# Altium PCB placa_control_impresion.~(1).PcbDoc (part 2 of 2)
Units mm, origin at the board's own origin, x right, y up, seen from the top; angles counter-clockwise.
Board outline 71.3 x 86.83 mm, 2 copper layers (Top Layer, Bottom Layer); 144 components, 32 nets, 580 pads, 404 vias.
Unrouted connection lines stored in the file: 1.
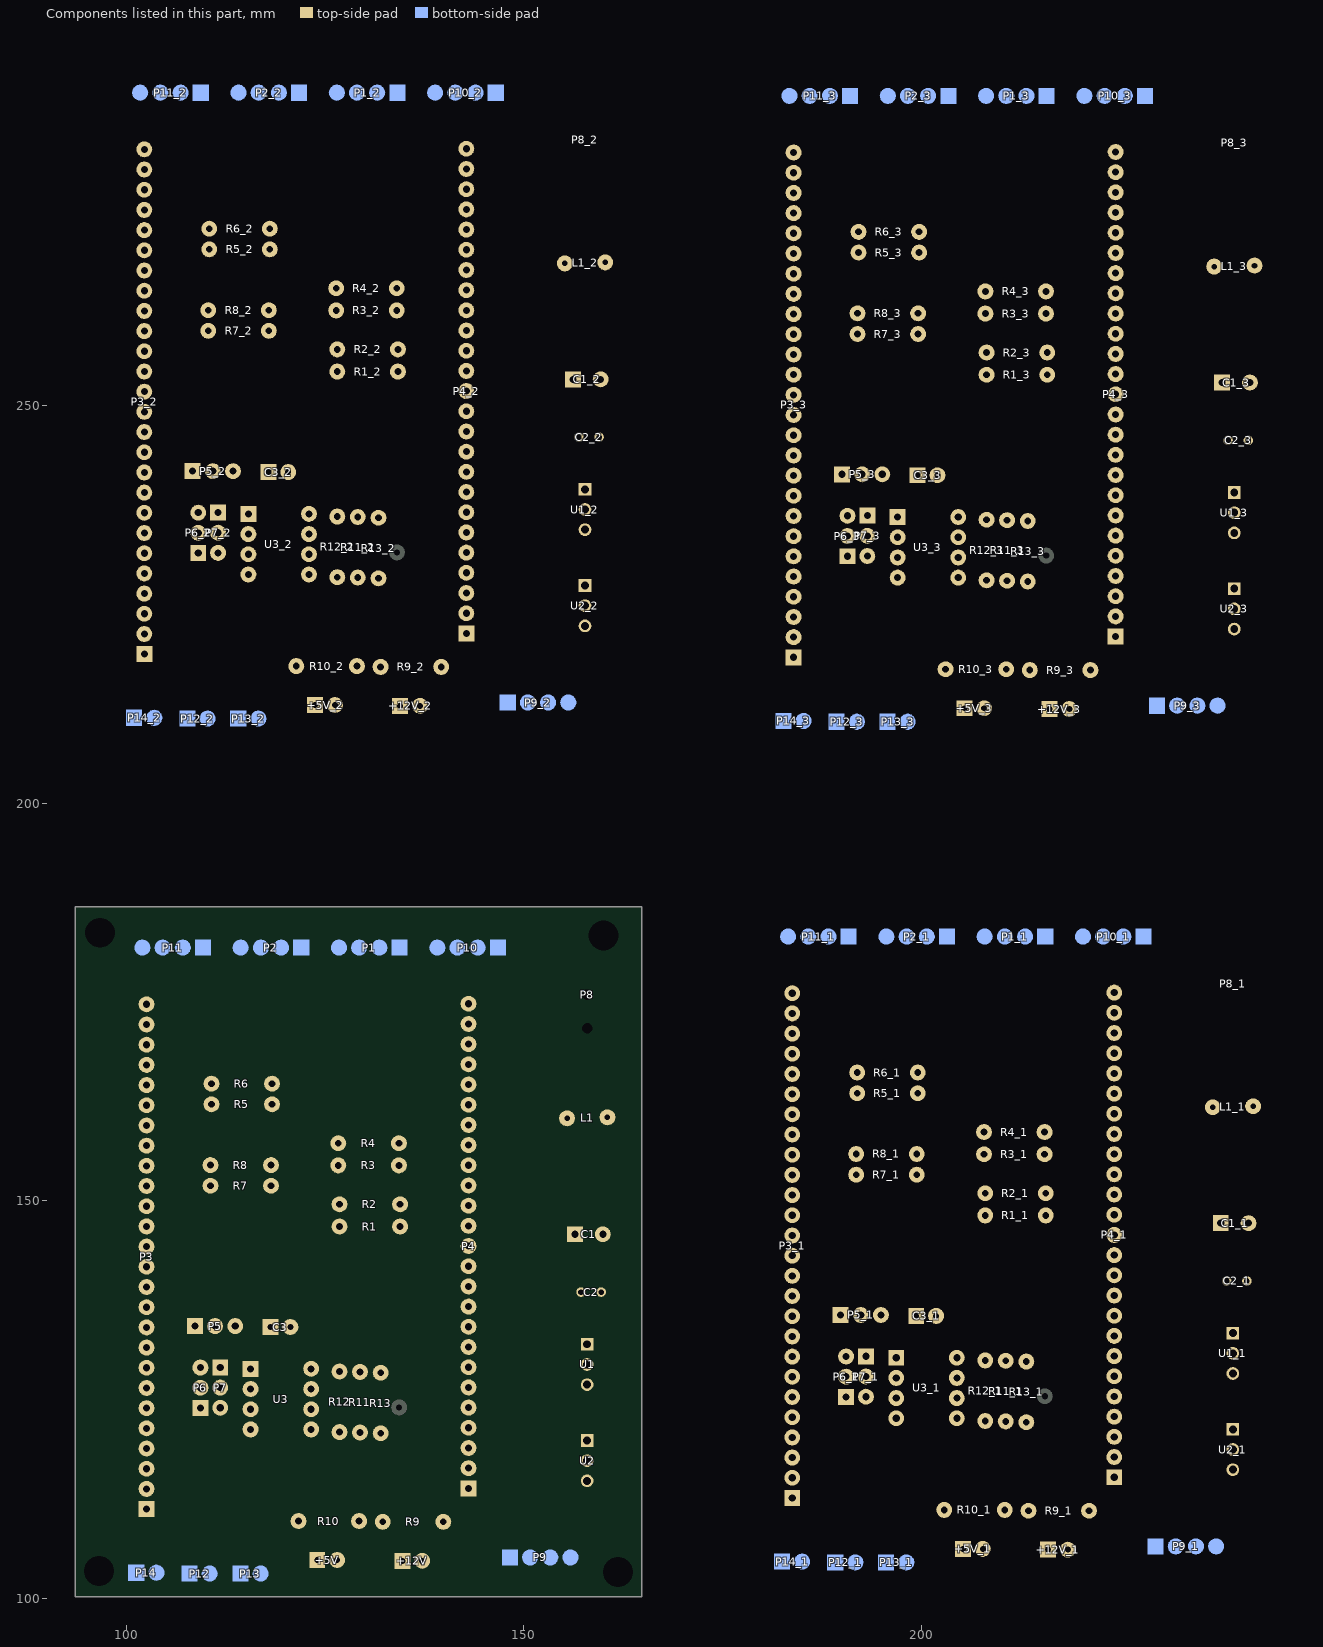
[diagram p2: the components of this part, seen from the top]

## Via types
v1: diameter 2, hole 0.711, Top Layer to Bottom Layer, 404 vias

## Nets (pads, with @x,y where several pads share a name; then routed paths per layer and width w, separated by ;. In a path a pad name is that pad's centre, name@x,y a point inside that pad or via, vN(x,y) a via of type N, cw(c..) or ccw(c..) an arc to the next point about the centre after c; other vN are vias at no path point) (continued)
pads on no net: +5V_1.1 +5V_1.2 +5V_2.1 +5V_2.2 +5V_3.1 +5V_3.2 +12V_1.1 +12V_1.2 +12V_2.1 +12V_2.2 +12V_3.1 +12V_3.2 C1_1.1 C1_1.2 C1_2.1 C1_2.2 C1_3.1 C1_3.2 C2_1.1 C2_1.2 C2_2.1 C2_2.2 C2_3.1 C2_3.2 C3_1.1 C3_1.2 C3_2.1 C3_2.2 C3_3.1 C3_3.2 L1_1.1 L1_1.2 L1_2.1 L1_2.2 L1_3.1 L1_3.2 P1_1.1 P1_1.2 P1_1.3 P1_1.4 P1_2.1 P1_2.2 P1_2.3 P1_2.4 P1_3.1 P1_3.2 P1_3.3 P1_3.4 P2_1.1 P2_1.2 P2_1.3 P2_1.4 P2_2.1 P2_2.2 P2_2.3 P2_2.4 P2_3.1 P2_3.2 P2_3.3 P2_3.4 P3.3 P3.4 P3.5 P3.10 P3.11 P3.12 P3.13 P3.18 P3.19 P3.22 P3.23 P3.24 P3.25 P3.26 P3_1.1 P3_1.2 P3_1.3 P3_1.4 P3_1.5 P3_1.6 P3_1.7 P3_1.8 P3_1.9 P3_1.10 P3_1.11 P3_1.12 P3_1.13 P3_1.14 P3_1.15 P3_1.16 P3_1.17 P3_1.18 P3_1.19 P3_1.20 P3_1.21 P3_1.22 P3_1.23 P3_1.24 P3_1.25 P3_1.26 P3_2.1 P3_2.2 P3_2.3 P3_2.4 P3_2.5 P3_2.6 P3_2.7 P3_2.8 P3_2.9 P3_2.10 P3_2.11 P3_2.12 P3_2.13 P3_2.14 P3_2.15 P3_2.16 P3_2.17 P3_2.18 P3_2.19 P3_2.20 P3_2.21 P3_2.22 P3_2.23 P3_2.24 P3_2.25 P3_2.26 P3_3.1 P3_3.2 P3_3.3 P3_3.4 P3_3.5 P3_3.6 P3_3.7 P3_3.8 P3_3.9 P3_3.10 P3_3.11 P3_3.12 P3_3.13 P3_3.14 P3_3.15 P3_3.16 P3_3.17 P3_3.18 P3_3.19 P3_3.20 P3_3.21 P3_3.22 P3_3.23 P3_3.24 P3_3.25 P3_3.26 P4.3 P4.4 P4.6 P4.7 P4.8 P4.9 P4.10 P4.11 P4.12 P4.13 P4.18 P4.19 P4.20 P4.22 P4.23 P4.24 P4.25 P4_1.1 P4_1.2 P4_1.3 P4_1.4 P4_1.5 P4_1.6 P4_1.7 P4_1.8 P4_1.9 P4_1.10 P4_1.11 P4_1.12 P4_1.13 P4_1.14 P4_1.15 P4_1.16 P4_1.17 P4_1.18 P4_1.19 P4_1.20 P4_1.21 P4_1.22 P4_1.23 P4_1.24 P4_1.25 P4_2.1 P4_2.2 P4_2.3 P4_2.4 P4_2.5 P4_2.6 P4_2.7 P4_2.8 P4_2.9 P4_2.10 P4_2.11 P4_2.12 P4_2.13 P4_2.14 P4_2.15 P4_2.16 P4_2.17 P4_2.18 P4_2.19 P4_2.20 P4_2.21 P4_2.22 P4_2.23 P4_2.24 P4_2.25 P4_3.1 P4_3.2 P4_3.3 P4_3.4 P4_3.5 P4_3.6 P4_3.7 P4_3.8 P4_3.9 P4_3.10 P4_3.11 P4_3.12 P4_3.13 P4_3.14 P4_3.15 P4_3.16 P4_3.17 P4_3.18 P4_3.19 P4_3.20 P4_3.21 P4_3.22 P4_3.23 P4_3.24 P4_3.25 P5_1.1 P5_1.2 P5_1.3 P5_2.1 P5_2.2 P5_2.3 P5_3.1 P5_3.2 P5_3.3 P6_1.1 P6_1.2 P6_1.3 P6_2.1 P6_2.2 P6_2.3 P6_3.1 P6_3.2 P6_3.3 P7_1.1 P7_1.2 P7_1.3 P7_2.1 P7_2.2 P7_2.3 P7_3.1 P7_3.2 P7_3.3 P8_1.2 P8_2.2 P8_3.2 P9_1.1 P9_1.2 P9_1.3 P9_1.4 P9_2.1 P9_2.2 P9_2.3 P9_2.4 P9_3.1 P9_3.2 P9_3.3 P9_3.4 P10_1.1 P10_1.2 P10_1.3 P10_1.4 P10_2.1 P10_2.2 P10_2.3 P10_2.4 P10_3.1 P10_3.2 P10_3.3 P10_3.4 P11_1.1 P11_1.2 P11_1.3 P11_1.4 P11_2.1 P11_2.2 P11_2.3 P11_2.4 P11_3.1 P11_3.2 P11_3.3 P11_3.4 P12_1.1 P12_1.2 P12_2.1 P12_2.2 P12_3.1 P12_3.2 P13_1.1 P13_1.2 P13_2.1 P13_2.2 P13_3.1 P13_3.2 P14_1.1 P14_1.2 P14_2.1 P14_2.2 P14_3.1 P14_3.2 R1_1.1 R1_1.2 R1_2.1 R1_2.2 R1_3.1 R1_3.2 R2_1.1 R2_1.2 R2_2.1 R2_2.2 R2_3.1 R2_3.2 R3_1.1 R3_1.2 R3_2.1 R3_2.2 R3_3.1 R3_3.2 R4_1.1 R4_1.2 R4_2.1 R4_2.2 R4_3.1 R4_3.2 R5_1.1 R5_1.2 R5_2.1 R5_2.2 R5_3.1 R5_3.2 R6_1.1 R6_1.2 R6_2.1 R6_2.2 R6_3.1 R6_3.2 R7_1.1 R7_1.2 R7_2.1 R7_2.2 R7_3.1 R7_3.2 R8_1.1 R8_1.2 R8_2.1 R8_2.2 R8_3.1 R8_3.2 R9_1.1 R9_1.2 R9_2.1 R9_2.2 R9_3.1 R9_3.2 R10_1.1 R10_1.2 R10_2.1 R10_2.2 R10_3.1 R10_3.2 R11_1.1 R11_1.2 R11_2.1 R11_2.2 R11_3.1 R11_3.2 R12_1.1 R12_1.2 R12_2.1 R12_2.2 R12_3.1 R12_3.2 R13_1.1 R13_1.2 R13_2.1 R13_2.2 R13_3.1 R13_3.2 U1_1.1 U1_1.2 U1_1.3 U1_2.1 U1_2.2 U1_2.3 U1_3.1 U1_3.2 U1_3.3 U2_1.1 U2_1.2 U2_1.3 U2_2.1 U2_2.2 U2_2.3 U2_3.1 U2_3.2 U2_3.3 U3_1.1 U3_1.2 U3_1.3 U3_1.4 U3_1.5 U3_1.6 U3_1.7 U3_1.8 U3_2.1 U3_2.2 U3_2.3 U3_2.4 U3_2.5 U3_2.6 U3_2.7 U3_2.8 U3_3.1 U3_3.2 U3_3.3 U3_3.4 U3_3.5 U3_3.6 U3_3.7 U3_3.8
copper on no net: | length 3999.1
  Bottom Layer w0.8: v1@98.525,269.65 110.43,269.65 110.44,269.64 110.44,272.3 ; v1(98.625,259.5) 97.15,259.5 96.175,258.525 96.175,219.75 97.135,218.79 v1(98.695,218.79) ; v1@98.625,272.19 v1@105.94,272.19 ; v1@98.665,221.39 v1@105.85,221.39 ; v1@98.665,223.93 v1@105.85,223.93 ; v1@98.665,226.47 v1@105.85,226.47 ; v1@98.665,229.01 v1@105.85,229.01 ; v1@98.665,231.55 109,231.55 109.05,231.5 ; v1@98.665,234.09 109,234.09 109.05,234.04 ; v1@98.665,236.63 109,236.63 109.05,236.58 ; v1(98.665,239.17) 107.395,239.17 108.225,240 114.225,240 115.4,241.175 115.4,254.95 113.825,256.525 113.825,279.675 109.37,284.13 109.37,289.405 ; v1@98.665,241.71 v1@105.825,241.71 ; v1@98.665,244.25 v1@105.85,244.25 ; v1@98.665,246.79 v1@105.85,246.79 ; v1@98.665,249.33 v1@105.85,249.33 ; v1(98.665,251.87) 106.73,251.87 108.35,250.25 108.35,241.8 ; v1(98.665,254.41) 107.115,254.41 110.89,250.635 110.89,241.8 ; v1(98.665,256.95) v1(105.85,256.95) ; v1@98.665,259.49 v1@105.85,259.49 ; v1@98.665,262.03 v1@105.85,262.03 ; v1@98.665,264.57 v1@105.85,264.57 ; v1@98.665,267.11 v1@105.85,267.11 ; v1@98.665,274.73 v1@105.85,274.73 ; v1@98.665,277.27 v1@105.85,277.27 ; v1@98.665,279.81 v1@105.85,279.81 ; v1@98.665,282.35 v1@105.85,282.35 ; v1@98.735,218.78 v1@105.92,218.78 ; v1@98.9,164.64 v1@106.215,164.64 ; v1@98.94,116.38 v1@106.125,116.38 ; v1@98.94,118.92 v1@106.125,118.92 ; v1@98.94,121.46 v1@106.125,121.46 ; v1@98.94,134.16 v1@106.1,134.16 ; v1@98.94,136.7 v1@106.125,136.7 ; v1@98.94,139.24 v1@106.125,139.24 ; v1@98.94,141.78 v1@106.125,141.78 ; v1@98.94,154.48 v1@106.125,154.48 ; v1@98.94,157.02 v1@106.125,157.02 ; v1@98.94,167.18 v1@106.125,167.18 ; v1@98.94,169.72 v1@106.125,169.72 ; v1@98.94,172.26 v1@106.125,172.26 ; v1@98.94,174.8 v1@106.125,174.8 ; 103.625,210.88 103.52,210.775 103.52,212.545 108.525,217.55 108.525,220.525 107.635,221.415 v1(105.825,221.415) ; v1(105.825,259.515) 110.21,259.515 110.375,259.35 ; v1(105.825,267.135) 110.56,267.135 112.625,269.2 112.625,279.175 106.83,284.97 106.83,289.405 ; v1@105.875,257.05 108.475,257.05 113.43,252.095 113.43,241.8 ; 110.315,259.45 110.315,262.05 ; 114.117,289.405 114.117,283.983 115.025,283.075 115.025,260.8 116.375,259.45 117.935,259.45 ; 115.359,228.805 116.53,228.805 116.912,229.187 ; 115.359,231.345 115.435,231.42 115.435,233.915 115.475,233.875 ; 116.62,210.675 116.62,217.377 122.089,222.845 124.395,222.845 126.2,224.65 130.9,224.65 134.125,227.875 134.125,231.55 ; 116.657,289.405 116.657,283.984 116.225,283.552 116.225,271.535 118.06,269.7 ; 121.39,217.275 121.675,217.275 123.75,215.2 123.75,212.375 ; 126.399,262.018 127.568,262.018 128.45,262.9 128.45,269.875 126.45,271.875 126.45,288.65 ; 126.549,254.327 129.65,257.428 129.65,270.375 129.15,270.875 129.15,289.375 ; 131.99,217.175 134.45,214.715 134.45,212.275 ; 133.95,264.925 133.95,262.087 134.019,262.018 138.942,262.018 138.96,262 v1(138.975,262.015) ; 134.019,264.81 134.019,270.194 136,272.175 v1(138.975,272.175) ; 134.169,254.327 138.907,254.327 v1(138.975,254.395) 136.005,254.395 135.95,254.45 ; 134.2,254.45 134.2,257.3 ; v1(138.975,256.935) 137.015,256.935 134.65,259.3 133.725,259.3 132.125,260.9 132.125,280.125 137.075,285.075 142.45,285.075 143.93,286.555 143.93,289.405 ; v1@139.28,221.39 v1@146.465,221.39 ; v1@139.28,226.47 v1@146.465,226.47 ; v1@139.28,229.01 v1@146.465,229.01 ; v1@139.28,231.55 v1@146.465,231.55 ; v1@139.28,234.09 v1@146.465,234.09 ; v1@139.28,236.63 v1@146.465,236.63 ; v1@139.28,239.17 v1@146.465,239.17 ; v1@139.28,241.71 v1@146.465,241.71 ; v1@139.28,244.25 v1@146.465,244.25 ; v1@139.28,246.79 v1@146.465,246.79 ; v1@139.28,249.33 v1@146.465,249.33 ; v1@139.28,251.87 v1@146.465,251.87 ; v1@139.28,254.41 v1@146.465,254.41 ; v1@139.28,256.95 v1@146.465,256.95 ; v1@139.28,259.49 147.04,259.49 148.4,260.85 148.4,284.45 146.47,286.38 146.47,289.405 ; v1@139.28,262.03 v1@146.465,262.03 ; v1@139.28,264.57 v1@146.465,264.57 ; v1@139.28,267.11 v1@146.465,267.11 ; v1@139.28,269.65 v1@146.465,269.65 ; v1@139.28,272.19 v1@146.465,272.19 ; v1@139.28,274.73 v1@146.465,274.73 ; v1@139.28,277.27 v1@146.465,277.27 ; v1@139.28,279.81 v1@146.465,279.81 ; v1@139.28,282.35 v1@146.465,282.35 ; v1@139.555,118.92 v1@146.74,118.92 ; v1@139.555,121.46 v1@146.74,121.46 ; v1@139.555,126.54 v1@146.74,126.54 ; v1@139.555,129.08 v1@146.74,129.08 ; v1@139.555,131.62 v1@146.74,131.62 ; v1@139.555,134.16 v1@146.74,134.16 ; v1@139.555,136.7 v1@146.74,136.7 ; v1@139.555,139.24 v1@146.74,139.24 ; v1@139.555,141.78 v1@146.74,141.78 ; v1@139.555,144.32 v1@146.74,144.32 ; v1@139.555,157.02 v1@146.74,157.02 ; v1@139.555,159.56 v1@146.74,159.56 ; v1@139.555,162.1 v1@146.74,162.1 ; v1@139.555,167.18 v1@146.74,167.18 ; v1@139.555,169.72 v1@146.74,169.72 ; v1@139.555,172.26 v1@146.74,172.26 ; v1@139.555,174.8 v1@146.74,174.8 ; 139.61,217.175 139.61,213.565 143.625,209.55 153.275,209.55 155.6,211.875 155.6,212.695 ; v1@180.025,163.5 191.93,163.5 191.94,163.49 191.94,166.15 ; v1(180.125,153.35) 178.65,153.35 177.675,152.375 177.675,113.6 178.635,112.64 v1(180.195,112.64) ; v1@180.125,166.04 v1@187.44,166.04 ; v1@180.165,115.24 v1@187.35,115.24 ; v1@180.165,117.78 v1@187.35,117.78 ; v1@180.165,120.32 v1@187.35,120.32 ; v1@180.165,122.86 v1@187.35,122.86 ; v1@180.165,125.4 190.5,125.4 190.55,125.35 ; v1@180.165,127.94 190.5,127.94 190.55,127.89 ; v1@180.165,130.48 190.5,130.48 190.55,130.43 ; v1(180.165,133.02) 188.895,133.02 189.725,133.85 195.725,133.85 196.9,135.025 196.9,148.8 195.325,150.375 195.325,173.525 190.87,177.98 190.87,183.255 ; v1@180.165,135.56 v1@187.325,135.56 ; v1@180.165,138.1 v1@187.35,138.1 ; v1@180.165,140.64 v1@187.35,140.64 ; v1@180.165,143.18 v1@187.35,143.18 ; v1(180.165,145.72) 188.23,145.72 189.85,144.1 189.85,135.65 ; v1(180.165,148.26) 188.615,148.26 192.39,144.485 192.39,135.65 ; v1(180.165,150.8) v1(187.35,150.8) ; v1@180.165,153.34 v1@187.35,153.34 ; v1@180.165,155.88 v1@187.35,155.88 ; v1@180.165,158.42 v1@187.35,158.42 ; v1@180.165,160.96 v1@187.35,160.96 ; v1@180.165,168.58 v1@187.35,168.58 ; v1@180.165,171.12 v1@187.35,171.12 ; v1@180.165,173.66 v1@187.35,173.66 ; v1@180.165,176.2 v1@187.35,176.2 ; v1@180.2,269.25 192.105,269.25 192.115,269.24 192.115,271.9 ; v1@180.235,112.63 v1@187.42,112.63 ; v1(180.3,259.1) 178.825,259.1 177.85,258.125 177.85,219.35 178.81,218.39 v1(180.37,218.39) ; v1@180.3,271.79 v1@187.615,271.79 ; v1@180.34,220.99 v1@187.525,220.99 ; v1@180.34,223.53 v1@187.525,223.53 ; v1@180.34,226.07 v1@187.525,226.07 ; v1@180.34,228.61 v1@187.525,228.61 ; v1@180.34,231.15 190.675,231.15 190.725,231.1 ; v1@180.34,233.69 190.675,233.69 190.725,233.64 ; v1@180.34,236.23 190.675,236.23 190.725,236.18 ; v1(180.34,238.77) 189.07,238.77 189.9,239.6 195.9,239.6 197.075,240.775 197.075,254.55 195.5,256.125 195.5,279.275 191.045,283.73 191.045,289.005 ; v1@180.34,241.31 v1@187.5,241.31 ; v1@180.34,243.85 v1@187.525,243.85 ; v1@180.34,246.39 v1@187.525,246.39 ; v1@180.34,248.93 v1@187.525,248.93 ; v1(180.34,251.47) 188.405,251.47 190.025,249.85 190.025,241.4 ; v1(180.34,254.01) 188.79,254.01 192.565,250.235 192.565,241.4 ; v1(180.34,256.55) v1(187.525,256.55) ; v1@180.34,259.09 v1@187.525,259.09 ; v1@180.34,261.63 v1@187.525,261.63 ; v1@180.34,264.17 v1@187.525,264.17 ; v1@180.34,266.71 v1@187.525,266.71 ; v1@180.34,274.33 v1@187.525,274.33 ; v1@180.34,276.87 v1@187.525,276.87 ; v1@180.34,279.41 v1@187.525,279.41 ; v1@180.34,281.95 v1@187.525,281.95 ; v1@180.41,218.38 v1@187.595,218.38 ; 185.125,104.73 185.02,104.625 185.02,106.395 190.025,111.4 190.025,114.375 189.135,115.265 v1(187.325,115.265) ; 185.3,210.48 185.195,210.375 185.195,212.145 190.2,217.15 190.2,220.125 189.31,221.015 v1(187.5,221.015) ; v1(187.325,153.365) 191.71,153.365 191.875,153.2 ; v1(187.325,160.985) 192.06,160.985 194.125,163.05 194.125,173.025 188.33,178.82 188.33,183.255 ; v1@187.375,150.9 189.975,150.9 194.93,145.945 194.93,135.65 ; v1(187.5,259.115) 191.885,259.115 192.05,258.95 ; v1(187.5,266.735) 192.235,266.735 194.3,268.8 194.3,278.775 188.505,284.57 188.505,289.005 ; v1@187.55,256.65 190.15,256.65 195.105,251.695 195.105,241.4 ; 191.815,153.3 191.815,155.9 ; 191.99,259.05 191.99,261.65 ; 195.617,183.255 195.617,177.833 196.525,176.925 196.525,154.65 197.875,153.3 199.435,153.3 ; 195.792,289.005 195.792,283.583 196.7,282.675 196.7,260.4 198.05,259.05 199.61,259.05 ; 196.859,122.655 198.03,122.655 198.412,123.037 ; 196.859,125.195 196.935,125.27 196.935,127.765 196.975,127.725 ; 197.034,228.405 198.205,228.405 198.587,228.787 ; 197.034,230.945 197.11,231.02 197.11,233.515 197.15,233.475 ; 198.12,104.525 198.12,111.227 203.589,116.695 205.895,116.695 207.7,118.5 212.4,118.5 215.625,121.725 215.625,125.4 ; 198.157,183.255 198.157,177.834 197.725,177.402 197.725,165.385 199.56,163.55 ; 198.295,210.275 198.295,216.977 203.764,222.445 206.07,222.445 207.875,224.25 212.575,224.25 215.8,227.475 215.8,231.15 ; 198.332,289.005 198.332,283.584 197.9,283.152 197.9,271.135 199.735,269.3 ; 202.89,111.125 203.175,111.125 205.25,109.05 205.25,106.225 ; 203.065,216.875 203.35,216.875 205.425,214.8 205.425,211.975 ; 207.899,155.868 209.068,155.868 209.95,156.75 209.95,163.725 207.95,165.725 207.95,182.5 ; 208.049,148.177 211.15,151.278 211.15,164.225 210.65,164.725 210.65,183.225 ; 208.074,261.618 209.243,261.618 210.125,262.5 210.125,269.475 208.125,271.475 208.125,288.25 ; 208.224,253.927 211.325,257.028 211.325,269.975 210.825,270.475 210.825,288.975 ; 213.49,111.025 215.95,108.565 215.95,106.125 ; 213.665,216.775 216.125,214.315 216.125,211.875 ; 215.45,158.775 215.45,155.937 215.519,155.868 220.442,155.868 220.46,155.85 v1(220.475,155.865) ; 215.519,158.66 215.519,164.044 217.5,166.025 v1(220.475,166.025) ; 215.625,264.525 215.625,261.687 215.694,261.618 220.617,261.618 220.635,261.6 v1(220.65,261.615) ; 215.669,148.177 220.407,148.177 v1(220.475,148.245) 217.505,148.245 217.45,148.3 ; 215.694,264.41 215.694,269.794 217.675,271.775 v1(220.65,271.775) ; 215.7,148.3 215.7,151.15 ; 215.844,253.927 220.582,253.927 v1(220.65,253.995) 217.68,253.995 217.625,254.05 ; 215.875,254.05 215.875,256.9 ; v1(220.475,150.785) 218.515,150.785 216.15,153.15 215.225,153.15 213.625,154.75 213.625,173.975 218.575,178.925 223.95,178.925 225.43,180.405 225.43,183.255 ; v1(220.65,256.535) 218.69,256.535 216.325,258.9 215.4,258.9 213.8,260.5 213.8,279.725 218.75,284.675 224.125,284.675 225.605,286.155 225.605,289.005 ; v1@220.78,115.24 v1@227.965,115.24 ; v1@220.78,120.32 v1@227.965,120.32 ; v1@220.78,122.86 v1@227.965,122.86 ; v1@220.78,125.4 v1@227.965,125.4 ; v1@220.78,127.94 v1@227.965,127.94 ; v1@220.78,130.48 v1@227.965,130.48 ; v1@220.78,133.02 v1@227.965,133.02 ; v1@220.78,135.56 v1@227.965,135.56 ; v1@220.78,138.1 v1@227.965,138.1 ; v1@220.78,140.64 v1@227.965,140.64 ; v1@220.78,143.18 v1@227.965,143.18 ; v1@220.78,145.72 v1@227.965,145.72 ; v1@220.78,148.26 v1@227.965,148.26 ; v1@220.78,153.34 228.54,153.34 229.9,154.7 229.9,178.3 227.97,180.23 227.97,183.255 ; v1@220.78,155.88 v1@227.965,155.88 ; v1@220.78,158.42 v1@227.965,158.42 ; v1@220.78,160.96 v1@227.965,160.96 ; v1@220.78,163.5 v1@227.965,163.5 ; v1@220.78,168.58 v1@227.965,168.58 ; v1@220.78,171.12 v1@227.965,171.12 ; v1@220.78,173.66 v1@227.965,173.66 ; v1@220.78,176.2 v1@227.965,176.2 ; v1@220.78,150.8 v1@227.965,150.8 ; v1@220.78,166.04 v1@227.965,166.04 ; v1@220.955,220.99 v1@228.14,220.99 ; v1@220.955,226.07 v1@228.14,226.07 ; v1@220.955,228.61 v1@228.14,228.61 ; v1@220.955,231.15 v1@228.14,231.15 ; v1@220.955,233.69 v1@228.14,233.69 ; v1@220.955,236.23 v1@228.14,236.23 ; v1@220.955,238.77 v1@228.14,238.77 ; v1@220.955,241.31 v1@228.14,241.31 ; v1@220.955,243.85 v1@228.14,243.85 ; v1@220.955,246.39 v1@228.14,246.39 ; v1@220.955,248.93 v1@228.14,248.93 ; v1@220.955,251.47 v1@228.14,251.47 ; v1@220.955,254.01 v1@228.14,254.01 ; v1@220.955,256.55 v1@228.14,256.55 ; v1@220.955,259.09 228.715,259.09 230.075,260.45 230.075,284.05 228.145,285.98 228.145,289.005 ; v1@220.955,261.63 v1@228.14,261.63 ; v1@220.955,264.17 v1@228.14,264.17 ; v1@220.955,266.71 v1@228.14,266.71 ; v1@220.955,269.25 v1@228.14,269.25 ; v1@220.955,271.79 v1@228.14,271.79 ; v1@220.955,274.33 v1@228.14,274.33 ; v1@220.955,276.87 v1@228.14,276.87 ; v1@220.955,279.41 v1@228.14,279.41 ; v1@220.955,281.95 v1@228.14,281.95 ; 221.11,111.025 221.11,107.415 225.125,103.4 234.775,103.4 237.1,105.725 237.1,106.545 ; 221.285,216.775 221.285,213.165 225.3,209.15 234.95,209.15 237.275,211.475 237.275,212.295
  Bottom Layer w1: 107.68,210.675 107.68,212.255 121.075,225.65 122.55,225.65 125.3,228.4 125.9,228.4 125.965,228.465 129.075,228.465 129.125,228.415 ; 110.22,210.675 110.22,212.815 121.655,224.25 123.795,224.25 125.98,226.435 129.835,226.435 131.725,228.325 131.725,229.75 127.201,234.274 126.551,234.274 126.551,236.085 126.591,236.125 ; 111.55,231.52 115.184,231.52 115.359,231.345 ; 111.55,234.06 112.485,234.06 114.875,236.45 ; 111.55,236.6 111.55,237.375 112.65,238.475 117.05,238.475 118.05,237.475 118.05,230.325 116.912,229.187 ; 112.15,234.35 112.25,234.35 ; 114.775,236.45 115.5,236.45 ; 115.34,231.82 115.435,231.725 ; 120.867,241.683 122.979,239.571 122.979,236.425 123.2,236.425 ; 122.979,233.885 127.59,233.885 ; 122.979,238.825 127.2,238.825 129.125,236.9 ; 123.671,231.345 126.291,228.725 ; 126.551,228.465 126.551,228.851 ; 129.01,217.275 129.01,217.985 134.955,223.93 142.78,223.93 142.785,223.925 v1@146.05,223.925 ; 129.125,235.125 129.125,235.375 130.932,233.568 135.182,233.568 136.05,232.7 136.05,224.025 ; 146.47,289.405 147.02,289.405 ; v1(146.7,223.975) 149.05,223.975 150.69,222.335 157.7,222.335 ; 150.52,212.695 150.52,222.155 ; 189.18,104.525 189.18,106.105 202.575,119.5 204.05,119.5 206.8,122.25 207.4,122.25 207.465,122.315 210.575,122.315 210.625,122.265 ; 189.355,210.275 189.355,211.855 202.75,225.25 204.225,225.25 206.975,228 207.575,228 207.64,228.065 210.75,228.065 210.8,228.015 ; 191.72,104.525 191.72,106.665 203.155,118.1 205.295,118.1 207.48,120.285 211.335,120.285 213.225,122.175 213.225,123.6 208.701,128.124 208.051,128.124 208.051,129.935 208.091,129.975 ; 191.895,210.275 191.895,212.415 203.33,223.85 205.47,223.85 207.655,226.035 211.51,226.035 213.4,227.925 213.4,229.35 208.876,233.874 208.226,233.874 208.226,235.685 208.266,235.725 ; 193.05,125.37 196.684,125.37 196.859,125.195 ; 193.05,127.91 193.985,127.91 196.375,130.3 ; 193.05,130.45 193.05,131.225 194.15,132.325 198.55,132.325 199.55,131.325 199.55,124.175 198.412,123.037 ; 193.225,231.12 196.859,231.12 197.034,230.945 ; 193.225,233.66 194.16,233.66 196.55,236.05 ; 193.225,236.2 193.225,236.975 194.325,238.075 198.725,238.075 199.725,237.075 199.725,229.925 198.587,228.787 ; 193.65,128.2 193.75,128.2 ; 193.825,233.95 193.925,233.95 ; 196.275,130.3 197,130.3 ; 196.45,236.05 197.175,236.05 ; 196.84,125.67 196.935,125.575 ; 197.015,231.42 197.11,231.325 ; 202.367,135.533 204.479,133.421 204.479,130.275 204.7,130.275 ; 202.542,241.283 204.654,239.171 204.654,236.025 204.875,236.025 ; 204.479,127.735 209.09,127.735 ; 204.479,132.675 208.7,132.675 210.625,130.75 ; 204.654,233.485 209.265,233.485 ; 204.654,238.425 208.875,238.425 210.8,236.5 ; 205.171,125.195 207.791,122.575 ; 205.346,230.945 207.966,228.325 ; 208.051,122.315 208.051,122.701 ; 208.226,228.065 208.226,228.451 ; 210.51,111.125 210.51,111.835 216.455,117.78 224.28,117.78 224.285,117.775 v1@227.55,117.775 ; 210.625,128.975 210.625,129.225 212.432,127.418 216.682,127.418 217.55,126.55 217.55,117.875 ; 210.685,216.875 210.685,217.585 216.63,223.53 224.455,223.53 224.46,223.525 v1@227.725,223.525 ; 210.8,234.725 210.8,234.975 212.607,233.168 216.857,233.168 217.725,232.3 217.725,223.625 ; 227.97,183.255 228.52,183.255 ; 228.145,289.005 228.695,289.005 ; v1(228.2,117.825) 230.55,117.825 232.19,116.185 239.2,116.185 ; v1(228.375,223.575) 230.725,223.575 232.365,221.935 239.375,221.935 ; 232.02,106.545 232.02,116.005 ; 232.195,212.295 232.195,221.755
  Bottom Layer w1.5: 101.75,289.405 101.75,290.825 103.625,292.7 148.875,292.7 151.5,290.075 151.5,233.15 153.725,230.925 157.7,230.925 ; 121.737,289.405 121.737,292.187 121.75,292.2 ; 131.99,216.685 131.99,217.175 ; 134.103,289.405 134.103,292.153 134.15,292.2 ; 138.85,289.405 138.85,292.125 138.925,292.2 ; 155.173,267.935 155.173,268.823 161.2,274.85 161.2,282.65 160.325,283.525 157.8,283.525 ; 155.6,212.695 155.6,213.525 160.55,218.475 160.55,221.7 ; 157.7,234.435 157.7,227.415 158.51,227.415 160.55,225.375 160.55,221.825 ; 157.7,239.515 157.7,245.25 156.15,246.8 156.15,260.975 160.253,265.078 160.253,268.062 ; 183.25,183.255 183.25,184.675 185.125,186.55 230.375,186.55 233,183.925 233,127 235.225,124.775 239.2,124.775 ; 183.425,289.005 183.425,290.425 185.3,292.3 230.55,292.3 233.175,289.675 233.175,232.75 235.4,230.525 239.375,230.525 ; 203.237,183.255 203.237,186.037 203.25,186.05 ; 203.412,289.005 203.412,291.787 203.425,291.8 ; 213.49,110.535 213.49,111.025 ; 213.665,216.285 213.665,216.775 ; 215.603,183.255 215.603,186.003 215.65,186.05 ; 215.778,289.005 215.778,291.753 215.825,291.8 ; 220.35,183.255 220.35,185.975 220.425,186.05 ; 220.525,289.005 220.525,291.725 220.6,291.8 ; 236.673,161.785 236.673,162.673 242.7,168.7 242.7,176.5 241.825,177.375 239.3,177.375 ; 236.848,267.535 236.848,268.423 242.875,274.45 242.875,282.25 242,283.125 239.475,283.125 ; 237.1,106.545 237.1,107.375 242.05,112.325 242.05,115.55 ; 237.275,212.295 237.275,213.125 242.225,218.075 242.225,221.3 ; 239.2,128.285 239.2,121.265 240.01,121.265 242.05,119.225 242.05,115.675 ; 239.2,133.365 239.2,139.1 237.65,140.65 237.65,154.825 241.753,158.928 241.753,161.912 ; 239.375,234.035 239.375,227.015 240.185,227.015 242.225,224.975 242.225,221.425 ; 239.375,239.115 239.375,244.85 237.825,246.4 237.825,260.575 241.928,264.678 241.928,267.662
  other v1: 187.395,112.655 220.475,115.225 180.125,115.25 228.1,115.245 98.9,116.39 106.1,116.405 180.125,117.79 220.45,117.78 187.325,117.805 139.25,118.905 98.9,118.93 146.875,118.925 106.1,118.945 220.475,120.305 180.125,120.33 228.1,120.325 187.325,120.345 139.25,121.445 98.9,121.47 146.875,121.465 106.1,121.485 220.475,122.845 180.125,122.87 228.1,122.865 187.325,122.885 220.475,125.385 180.125,125.41 228.1,125.405 187.325,125.425 139.25,126.525 146.875,126.545 220.475,127.925 180.125,127.95 228.1,127.945 187.325,127.965 139.25,129.065 146.875,129.085 220.475,130.465 180.125,130.49 228.1,130.485 187.325,130.505 139.25,131.605 146.875,131.625 220.475,133.005 187.325,133.02 228.1,133.025 139.25,134.145 98.9,134.17 146.875,134.165 106.1,134.185 220.475,135.545 180.125,135.57 228.1,135.565 187.325,135.585 139.25,136.685 98.9,136.71 146.875,136.705 106.1,136.725 220.475,138.085 180.125,138.11 228.1,138.105 187.325,138.125 139.25,139.225 98.9,139.25 146.875,139.245 106.1,139.265 220.475,140.625 180.125,140.65 228.1,140.645 187.325,140.665 139.25,141.765 98.9,141.79 146.875,141.785 106.1,141.805 220.475,143.165 180.125,143.19 228.1,143.185 187.325,143.205 139.25,144.305 146.875,144.325 220.475,145.705 187.35,145.72 228.1,145.725 187.35,148.26 228.1,148.265 228.1,150.805 220.475,153.325 98.9,154.49 106.1,154.505 180.125,155.89 228.1,155.885 187.325,155.905 139.25,157.005 98.9,157.03 146.875,157.025 106.1,157.045 220.475,158.405 180.125,158.43 228.1,158.425 187.325,158.445 139.25,159.545 146.875,159.565 220.475,160.945 180.125,160.97 228.1,160.965 139.25,162.085 146.875,162.105 220.475,163.485 180.125,163.51 228.1,163.505 187.325,163.525 98.9,164.65 106.1,164.665 180.125,166.05 228.1,166.045 187.325,166.065 139.25,167.165 98.9,167.19 146.875,167.185 106.1,167.205 220.475,168.565 180.125,168.59 228.1,168.585 187.325,168.605 139.25,169.705 98.9,169.73 146.875,169.725 106.1,169.745 220.475,171.105 180.125,171.13 228.1,171.125 187.325,171.145 139.25,172.245 98.9,172.27 146.875,172.265 106.1,172.285 220.475,173.645 180.125,173.67 228.1,173.665 187.325,173.685 139.25,174.785 98.9,174.81 146.875,174.805 106.1,174.825 220.475,176.185 180.125,176.21 228.1,176.205 187.325,176.225 187.57,218.405 105.895,218.805 220.65,220.975 180.3,221 228.275,220.995 138.975,221.375 146.6,221.395 98.625,221.4 220.625,223.53 180.3,223.54 187.5,223.555 138.95,223.93 98.625,223.94 105.825,223.955 220.65,226.055 180.3,226.08 187.5,226.095 228.275,226.075 138.975,226.455 146.6,226.475 98.625,226.48 105.825,226.495 220.65,228.595 180.3,228.62 187.5,228.635 228.275,228.615 138.975,228.995 146.6,229.015 98.625,229.02 105.825,229.035 220.65,231.135 180.3,231.16 187.5,231.175 228.275,231.155 138.975,231.535 146.6,231.555 98.625,231.56 105.825,231.575 220.65,233.675 180.3,233.7 187.5,233.715 228.275,233.695 138.975,234.075 146.6,234.095 98.625,234.1 105.825,234.115 220.65,236.215 180.3,236.24 187.5,236.255 228.275,236.235 138.975,236.615 146.6,236.635 98.625,236.64 105.825,236.655 187.5,238.77 220.65,238.755 228.275,238.775 105.825,239.17 138.975,239.155 146.6,239.175 220.65,241.295 180.3,241.32 187.5,241.335 228.275,241.315 138.975,241.695 146.6,241.715 98.625,241.72 105.825,241.735 220.65,243.835 180.3,243.86 187.5,243.875 228.275,243.855 138.975,244.235 146.6,244.255 98.625,244.26 105.825,244.275 220.65,246.375 180.3,246.4 187.5,246.415 228.275,246.395 138.975,246.775 146.6,246.795 98.625,246.8 105.825,246.815 220.65,248.915 180.3,248.94 187.5,248.955 228.275,248.935 138.975,249.315 146.6,249.335 98.625,249.34 105.825,249.355 187.525,251.47 220.65,251.455 228.275,251.475 105.85,251.87 138.975,251.855 146.6,251.875 187.525,254.01 228.275,254.015 105.85,254.41 146.6,254.415 228.275,256.555 146.6,256.955 220.65,259.075 138.975,259.475 180.3,261.64 187.5,261.655 228.275,261.635 146.6,262.035 98.625,262.04 105.825,262.055 220.65,264.155 180.3,264.18 187.5,264.195 228.275,264.175 138.975,264.555 146.6,264.575 98.625,264.58 105.825,264.595 220.65,266.695 180.3,266.72 228.275,266.715 138.975,267.095 146.6,267.115 98.625,267.12 220.65,269.235 180.3,269.26 187.5,269.275 228.275,269.255 138.975,269.635 146.6,269.655 98.625,269.66 105.825,269.675 180.3,271.8 187.5,271.815 228.275,271.795 146.6,272.195 98.625,272.2 105.825,272.215 220.65,274.315 180.3,274.34 187.5,274.355 228.275,274.335 138.975,274.715 146.6,274.735 98.625,274.74 105.825,274.755 220.65,276.855 180.3,276.88 187.5,276.895 228.275,276.875 138.975,277.255 146.6,277.275 98.625,277.28 105.825,277.295 220.65,279.395 180.3,279.42 187.5,279.435 228.275,279.415 138.975,279.795 146.6,279.815 98.625,279.82 105.825,279.835 220.65,281.935 180.3,281.96 187.5,281.975 228.275,281.955 138.975,282.335 146.6,282.355 98.625,282.36 105.825,282.375

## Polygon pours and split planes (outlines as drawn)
no net on Bottom Layer "plano_señal_fuerte" (solid, remove dead copper, pour order 1000): 175,294.189 175.062,294.225 246.3,294.225 246.269,294.207 246.269,207.443 246.3,207.425 175.156,207.425 175.062,207.48 175,207.516
no net on Bottom Layer "plano_señal_fuerte" (solid, remove dead copper, pour order 1000): 93.325,294.589 93.387,294.625 164.625,294.625 164.594,294.607 164.594,207.843 164.625,207.825 93.481,207.825 93.387,207.88 93.325,207.916
no net on Bottom Layer "plano_señal_fuerte" (solid, remove dead copper, pour order 1000): 174.825,188.439 174.887,188.475 246.125,188.475 246.094,188.457 246.094,101.693 246.125,101.675 174.981,101.675 174.887,101.73 174.825,101.766
GND on Bottom Layer "plano_señal_fuerte" (solid, remove dead copper, pour order 1000): 93.6,187.039 93.662,187.075 164.9,187.075 164.869,187.057 164.869,100.293 164.9,100.275 93.756,100.275 93.662,100.33 93.6,100.366

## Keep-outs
Drill Guide:
  rectangle: 181.7,213.675 227.1,283.875
  rectangle: 100.025,214.075 145.425,284.275
  rectangle: 181.525,107.925 226.925,178.125
  rectangle: 100.3,106.525 145.7,176.725

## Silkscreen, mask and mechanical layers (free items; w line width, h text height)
Top Overlay:
  lines w0.254: 134.05,231.575 138.935,231.575 138.975,231.535 ; 134.325,124.025 139.21,124.025 139.25,123.985 ; 215.55,125.425 220.435,125.425 220.475,125.385 ; 215.725,231.175 220.61,231.175 220.65,231.135
Drill Drawing:
  lines w0.254: 93.425,72.425 93.475,72.475

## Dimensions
91.375,190.675 to 89.933,43.649 on Drill Drawing
165.875,38.05 to 92.95,39.475 on Drill Drawing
